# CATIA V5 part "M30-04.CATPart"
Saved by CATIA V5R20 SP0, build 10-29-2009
Part number: M30-04
Revision: ANY
Definition: UNKNOWN
Nomenclature: M30-04
Source: Unknown
Bounding box of the stored display mesh (mm): x -65 to 65, y -64.818 to 64.818, z 0 to 12
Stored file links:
  C:\Users\Utente\Desktop\IO LAVORO\3D X SITO CF\X 3D SITO CF 27-09-2020\740T\740T-30\M30-04.CATPart
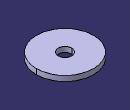
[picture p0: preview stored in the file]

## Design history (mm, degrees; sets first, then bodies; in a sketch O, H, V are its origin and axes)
Body1 "NONE" (main body)
  Solid1: solid without history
